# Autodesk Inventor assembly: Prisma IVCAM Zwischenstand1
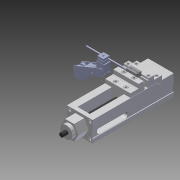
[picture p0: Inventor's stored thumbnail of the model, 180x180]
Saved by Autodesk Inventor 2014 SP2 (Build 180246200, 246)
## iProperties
Created: 2015-07
Part Number: Prisma IVCAM Zwischenstand1
Document SubType Name: Assembly
Designer: e_krauts
Mass: 4561.57 g
Surface Area: 5905.42 cm^2
Volume: 4561.57 cm^3
Density: 1 g/cm^3
Author: e_krauts
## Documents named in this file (5)
- C:\SolidCAM_Temp\PRISMA IVCAM ZWISCHENSTAND1\DesignModel.iam
- C:\SolidCAM_Temp\PRISMA IVCAM ZWISCHENSTAND1\Schraubstock_Blank.iam
- C:\SolidCAM_Temp\PRISMA IVCAM ZWISCHENSTAND1\Werkstückanschlag.iam
- C:\SolidCAM_Temp\PRISMA IVCAM ZWISCHENSTAND1\Prisma mit Passfedernut-01.ipt
- C:\SolidCAM_Temp\PRISMA IVCAM ZWISCHENSTAND1\Prisma mit Passfedernut.ipt
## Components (3 placed, 3 different names)
1. Schraubstock_Blank:1 [sub-assembly] — Fluchtend:1, Passend:1, Passend:2, Passend:3
2. Werkstückanschlag:1 [sub-assembly] — Fluchtend:1, Passend:4
3. Prisma mit Passfedernut-01:1 — Passend:1, Passend:2, Passend:3, Passend:4
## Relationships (5: Mate 4, Flush 1)
- Fluchtend:1 [Flush]: Schraubstock_Blank:1 ↔ Werkstückanschlag:1
- Passend:1 [Mate]: Schraubstock_Blank:1 ↔ Prisma mit Passfedernut-01:1
- Passend:2 [Mate]: Schraubstock_Blank:1 ↔ Prisma mit Passfedernut-01:1
- Passend:3 [Mate]: Schraubstock_Blank:1 ↔ Prisma mit Passfedernut-01:1
- Passend:4 [Mate]: Werkstückanschlag:1 ↔ Prisma mit Passfedernut-01:1
